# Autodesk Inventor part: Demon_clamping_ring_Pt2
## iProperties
Shininess: 64.0
Length Units: 11269
Angle Units: 11279
Time Units: 11290
Mass Units: 11283
Length Display Precision: 3
Angle Display Precision: 2
Compacted: True
Part Number: Demon_clamping_ring_Pt2
Document SubType Name: Modeling
Created: 2005-04
Designer: John Blackburn
Manufacturer: Standard
Standards Organization: Custom
Material: Aluminum-6061
Density: 0.0
Volumn: 0.0
Area: 0.0
PropertySet Name: Model Information
Control State: 0
Master: False
Checked Out: False
Author: John Blackburn
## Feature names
1. Extrusion1
2. Extrusion2
